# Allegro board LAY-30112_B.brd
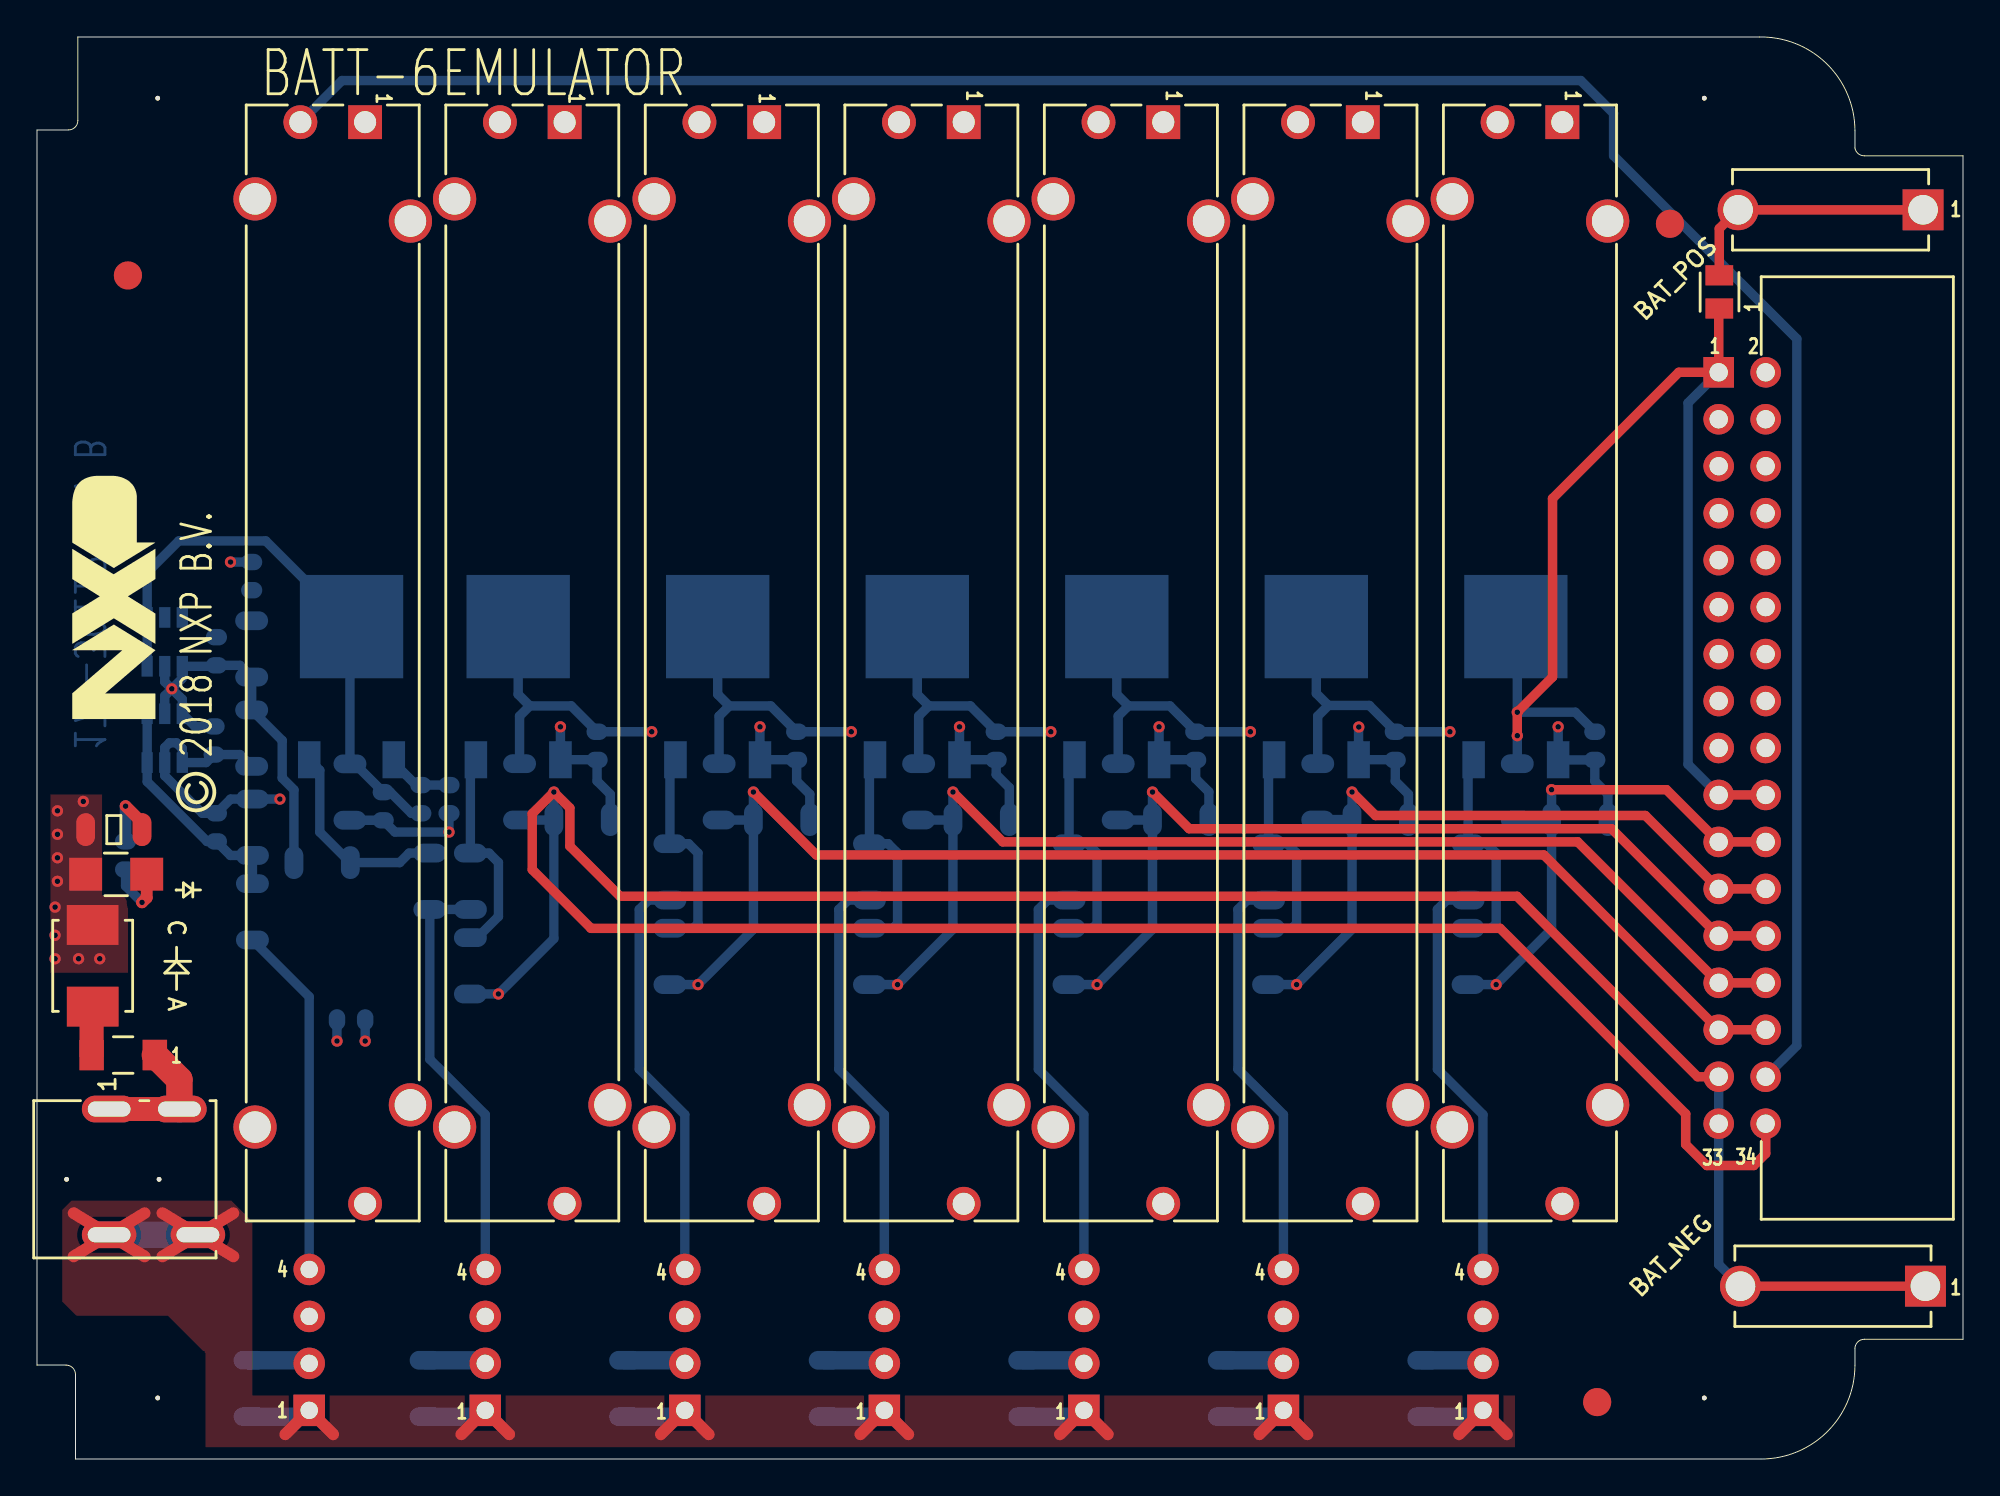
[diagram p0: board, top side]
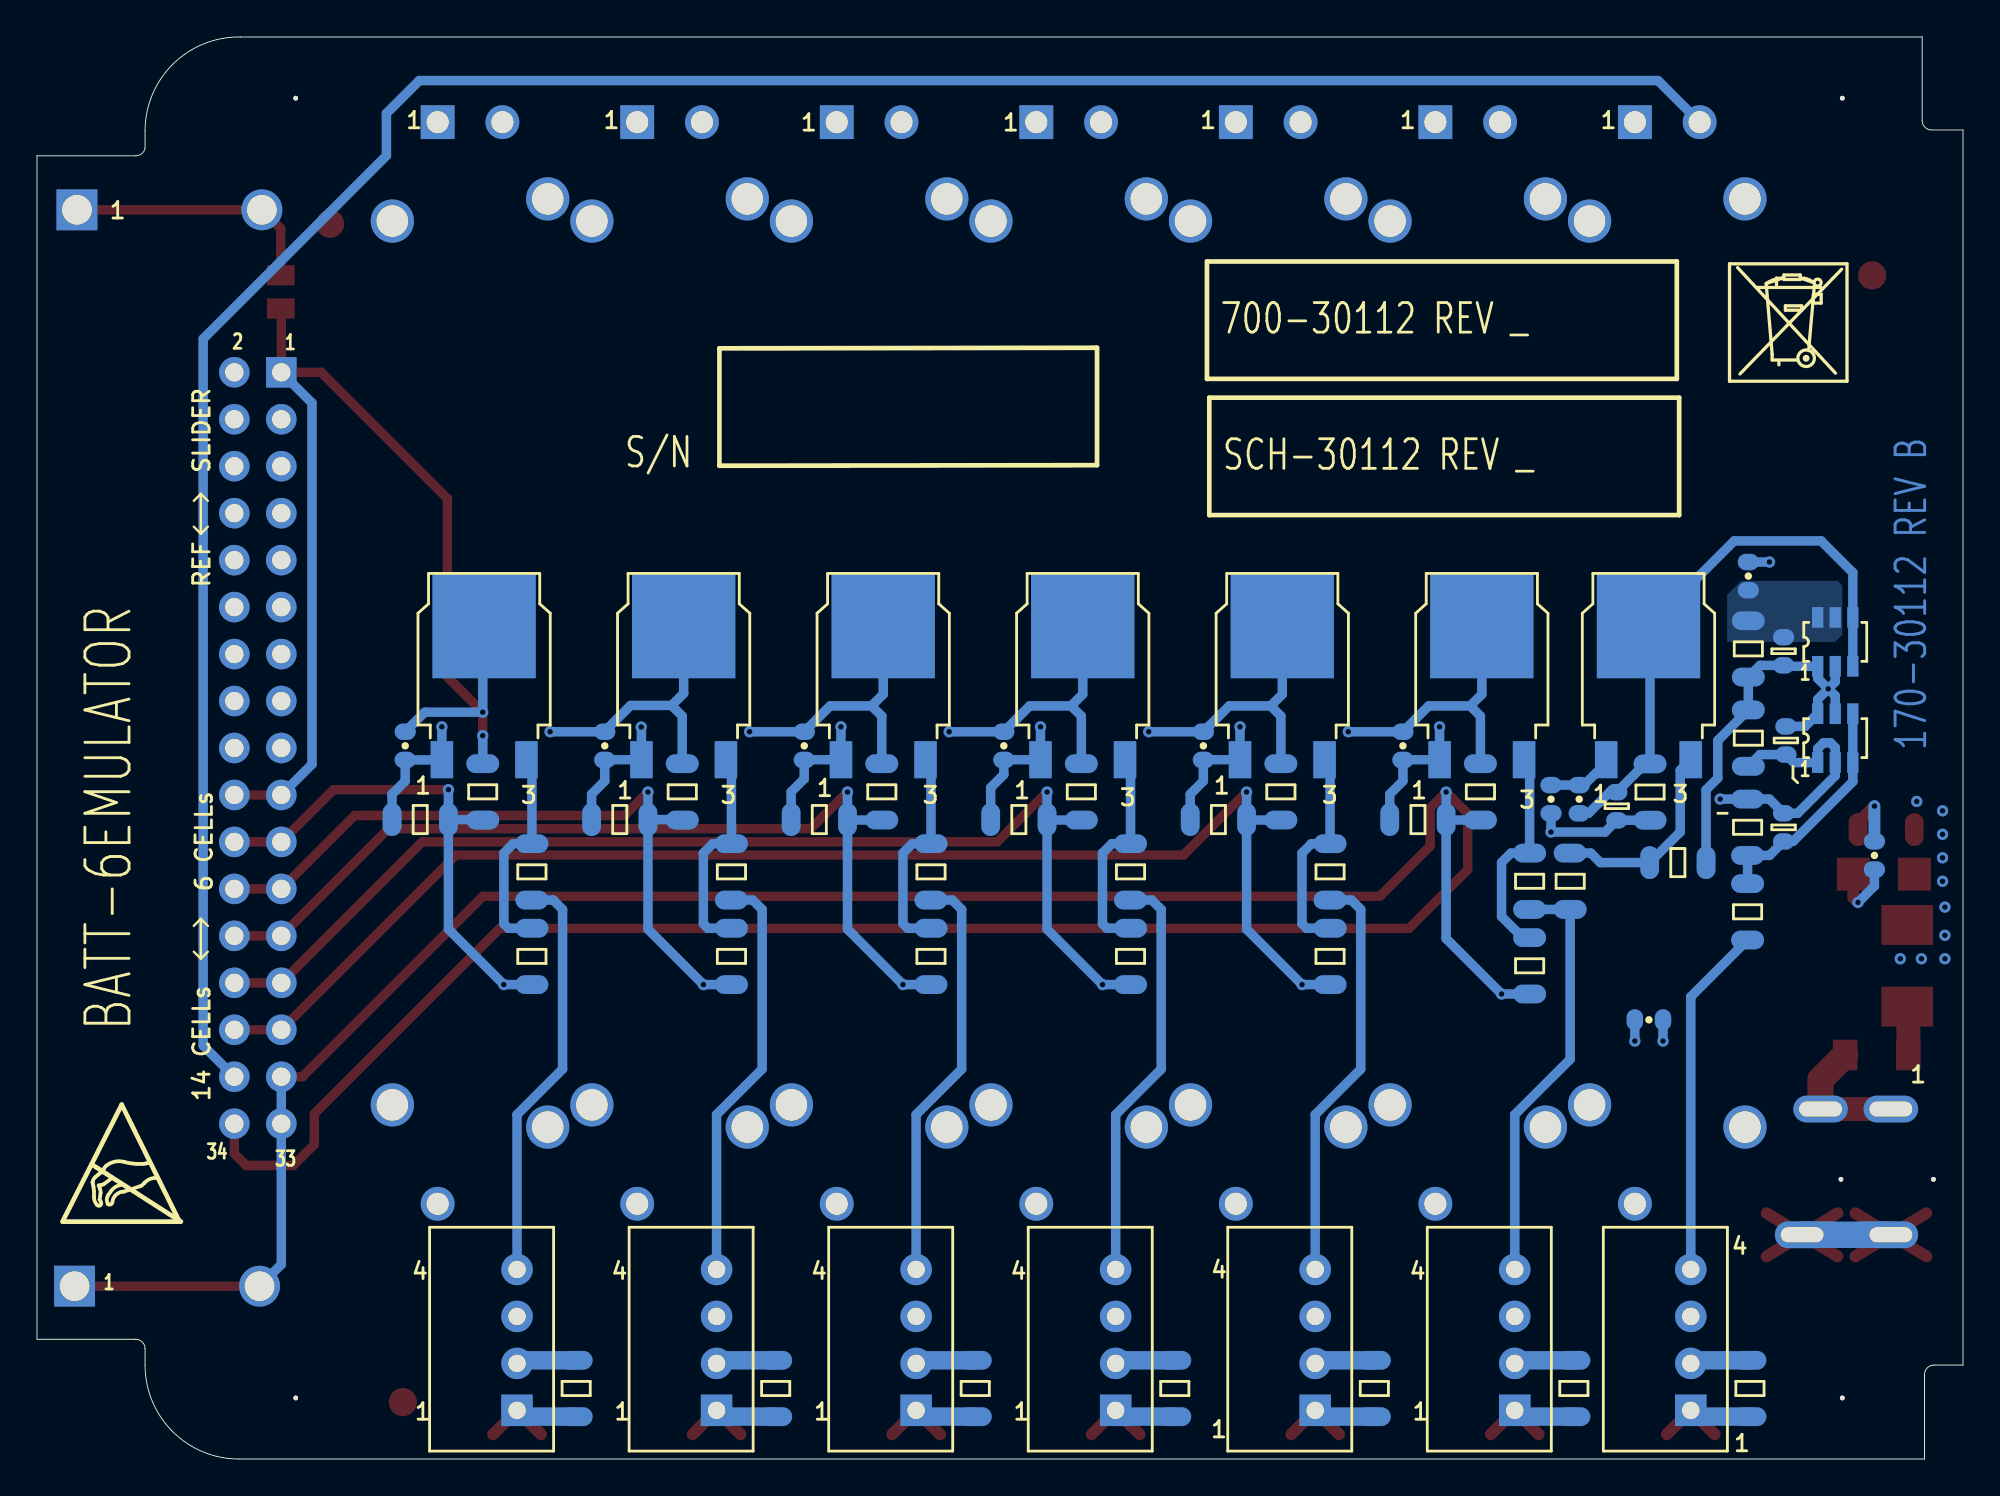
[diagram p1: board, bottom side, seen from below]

Outline 104.13 x 76.91 mm; copper layers: TOP, L2_SIG1, L3_SIG2, BOTTOM. Coordinates in mm from the lower left corner of the outline.
Outline path: 0,71.88 0,5.08 1.57,5.08 arc(1.93,4.93) 2.08,4.57 2.08,0 93.2,0 arc(96.8,1.49) 98.28,5.08 98.28,5.97 arc(98.43,6.33) 98.79,6.48 104.13,6.48 104.13,70.49 98.78,70.49 arc(98.46,70.6) 98.28,70.9 98.28,71.83 arc(96.77,75.46) 93.12,76.91 2.21,76.91 2.21,72.39 arc(2.06,72.03) 1.7,71.88 0,71.88

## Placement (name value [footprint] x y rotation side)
C29  1UF  [CC1206_OV]  29.47 34.59 180 bottom
C30  10uF  [CC1206_OV]  23.43 26.68 270 bottom
C31  100uF  [CC1206_OV]  26.09 36.08 270 bottom
C32  10uF  [CC1206_OV]  21.04 3.82 270 bottom
C37  10uF  [CC1206_OV]  34.22 27.18 270 bottom
C38  1UF  [CC1206_OV]  40.26 34.59 180 bottom
C39  100uF  [CC1206_OV]  36.88 36.08 270 bottom
C40  10uF  [CC1206_OV]  31.83 3.82 270 bottom
C41  10uF  [CC1206_OV]  45.01 27.18 270 bottom
C42  1UF  [CC1206_OV]  51.04 34.59 180 bottom
C43  100uF  [CC1206_OV]  47.67 36.08 270 bottom
C44  10uF  [CC1206_OV]  42.61 3.82 270 bottom
C45  1UF  [CC1206_OV]  61.83 34.59 180 bottom
C46  10uF  [CC1206_OV]  55.79 27.18 270 bottom
C47  100uF  [CC1206_OV]  58.45 36.08 270 bottom
C48  10uF  [CC1206_OV]  53.4 3.82 270 bottom
C49  1UF  [CC1206_OV]  72.62 34.59 180 bottom
C50  10uF  [CC1206_OV]  66.58 27.18 270 bottom
C51  100uF  [CC1206_OV]  69.24 36.08 270 bottom
C52  10uF  [CC1206_OV]  64.19 3.82 270 bottom
C53  10uF  [CC1206_OV]  77.37 27.18 270 bottom
C54  1UF  [CC1206_OV]  83.41 34.59 180 bottom
C55  100uF  [CC1206_OV]  80.03 36.08 270 bottom
C56  10uF  [CC1206_OV]  74.98 3.82 270 bottom
C63  10uF  [CC1206_OV]  15.42 32.26 180 bottom
C64  10uF  [CC1206_OV]  16.92 36.07 270 bottom
C65  10uF  [CC1206_OV]  11.52 3.82 270 bottom
C66  10uF  [CC1206_OV]  11.65 34.17 90 bottom
C67  10uF  [CC1206_OV]  11.61 38.99 270 bottom
C68  47uF  [CC1206_OV]  4.15 34.04 0 top
C69  10uF  [CC1206_OV]  11.61 43.81 270 bottom
C70  0.1uF  [CC0603_OV]  18.72 35.31 270 bottom
C71  0.1uF  [CC0603_OV]  9.7 43.69 270 bottom
C72  0.1uF  [CC0603_OV]  9.7 34.16 90 bottom
C73  0.1uF  [CC0603_OV]  9.57 38.86 270 bottom
D2  LED RED  [1206LD]  4.28 31.63 180 top
D3  SS24T3G  [CASE403A_03]  3.01 26.68 270 top
F1  SF-1206SP400-2  [FUSE_3P2X1P65]  4.66 21.85 180 top
F2  F0805B0R25FSTR  [FUSE_1P8_2P2X1P5]  90.95 63.12 90 top
J1  CON 2x17  [HDR217_RA_TH]  90.92 58.78 0 top
J2  BANANA RED  [BANANA_930224]  101.97 67.56 180 top
J6  PJ-053DH  [CON_3_DC_PWR_JACK_TH]  3.9 18.93 270 top
J23  BANANA BLACK  [BANANA_930224]  102.09 9.35 180 top
NOREF  -  []  33.36 17.95 90 top
NOREF#2  -  []  67.39 10.25 0 top
NOREF#3  -  []  28.78 -11.14 90 top
NOREF#4  -  [unnamed#2]  90.14 73.6 0 top
NOREF#5  -  []  33.22 -11.14 0 top
NOREF#6  -  []  93.4 63.77 0 top
NOREF#7  -  [unnamed#2]  84.35 3.08 0 top
NOREF#8  -  []  52.55 66.95 90 top
NOREF#9  -  []  45.81 10.25 0 top
NOREF#10  -  []  22.58 17.95 90 top
NOREF#11  -  []  14.72 2.63 90 top
NOREF#12  -  []  8.7 12.13 90 top
NOREF#13  -  []  90.92 18.14 0 top
NOREF#14  -  []  54.64 13.05 90 top
NOREF#15  -  []  6.26 19.47 0 top
NOREF#16  -  []  41.76 19.15 90 top
NOREF#17  -  []  1.35 19.2 90 top
NOREF#18  -  []  35.81 72.3 0 top
NOREF#19  -  []  0 5.9 0 top
NOREF#20  -  []  78.17 10.25 0 top
NOREF#21  -  []  46.6 72.3 0 top
NOREF#22  -  []  24.23 2.63 90 top
NOREF#23  -  []  35.81 72.3 0 top
NOREF#24  -  [unnamed#2]  90.14 3.3 0 top
NOREF#25  -  []  84.92 19.15 90 top
NOREF#26  -  []  6.57 12.36 0 top
NOREF#27  -  []  1.6 15.13 0 top
NOREF#28  -  []  2.95 21.85 0 top
NOREF#29  -  []  82.72 -11.14 90 top
NOREF#30  -  []  76.37 -11.14 0 top
NOREF#31  -  []  1.35 28.7 0 top
NOREF#32  -  []  6.57 0.61 90 top
NOREF#33  -  []  12.92 12.36 0 top
NOREF#34  -  []  50.36 -11.14 90 top
NOREF#35  -  []  44.01 0.61 0 top
NOREF#36  -  []  14.24 72.3 0 top
NOREF#37  -  []  57.39 72.3 0 top
NOREF#38  -  []  65.73 17.95 90 top
NOREF#39  -  []  65.43 13.05 90 top
NOREF#40  -  []  30.98 19.15 90 top
NOREF#41  -  []  44.01 -11.14 0 top
NOREF#42  -  []  22.43 0.61 0 top
NOREF#43  -  []  54.94 17.95 90 top
NOREF#44  -  []  30.98 66.95 90 top
NOREF#45  -  []  -16.87 -28.01 0 top
NOREF#46  -  []  6.57 0.61 0 top
NOREF#47  -  []  104.13 7.77 0 top
NOREF#48  -  []  84.92 66.95 90 top
NOREF#49  -  []  76.22 13.05 90 top
NOREF#50  -  []  90.92 18.14 90 top
NOREF#51  -  []  -464.54 -272.99 0 top
NOREF#52  -  []  46.6 72.3 0 top
NOREF#53  -  []  67.39 2.63 90 top
NOREF#54  -  []  61.15 -11.14 90 top
NOREF#55  -  [unnamed#2]  6.53 73.6 0 top
NOREF#56  -  []  1.6 15.13 0 top
NOREF#57  -  []  57.39 72.3 0 top
NOREF#58  -  []  76.37 0.61 0 top
NOREF#59  -  []  76.52 17.95 90 top
NOREF#60  -  []  24.23 10.25 0 top
NOREF#61  -  []  11.49 13.05 90 top
NOREF#62  -  []  2.96 76.91 0 top
NOREF#63  -  []  65.59 -11.14 0 top
NOREF#64  -  []  22.43 -11.14 0 top
NOREF#65  -  []  76.22 73.05 0 top
NOREF#66  -  []  6.53 73.6 0 top
NOREF#67  -  []  20.19 66.95 90 top
NOREF#68  -  []  33.06 13.05 90 top
NOREF#69  -  []  20.19 19.15 90 top
NOREF#70  -  []  71.94 -11.14 90 top
NOREF#71  -  [unnamed#2]  6.53 3.3 0 top
NOREF#72  -  []  25.03 72.3 0 top
NOREF#73  -  []  25.03 72.3 0 top
NOREF#74  -  []  54.64 73.05 0 top
NOREF#75  -  []  -438.51 252.15 0 top
NOREF#76  -  []  6.53 3.3 0 top
NOREF#77  -  []  54.8 0.61 0 top
NOREF#78  -  []  78.97 72.3 0 top
NOREF#79  -  []  45.81 2.63 90 top
NOREF#80  -  []  6.53 3.3 0 top
NOREF#81  -  []  43.85 73.05 0 top
NOREF#82  -  []  14.24 72.3 0 top
NOREF#83  -  []  78.17 2.63 90 top
NOREF#84  -  []  2.08 1.28 0 top
NOREF#85  -  []  52.55 19.15 90 top
NOREF#86  -  []  65.59 0.61 0 top
NOREF#87  -  []  35.02 10.25 0 top
NOREF#88  -  []  22.28 73.05 0 top
NOREF#89  -  []  63.34 66.95 90 top
NOREF#90  -  []  93.46 23.22 0 top
NOREF#91  -  []  6.53 3.3 0 top
NOREF#92  -  []  6.4 40.03 90 top
NOREF#93  -  []  43.85 13.05 90 top
NOREF#94  -  []  90.14 3.3 0 top
NOREF#95  -  []  11.79 17.95 90 top
NOREF#96  -  []  44.15 17.95 90 top
NOREF#97  -  []  56.6 10.25 0 top
NOREF#98  -  []  74.13 66.95 90 top
NOREF#99  -  []  8.62 36.07 90 top
NOREF#100  -  []  33.06 73.05 0 top
NOREF#101  -  [unnamed#2]  88.28 66.81 0 top
NOREF#102  -  []  69.58 61.21 0 top
NOREF#103  -  []  1.6 15.13 90 top
NOREF#104  -  []  144.02 63.77 90 top
NOREF#105  -  []  74.13 19.15 90 top
NOREF#106  -  []  41.76 66.95 90 top
NOREF#107  -  []  98.49 70.58 0 top
NOREF#108  -  []  22.28 13.05 90 top
NOREF#109  -  []  68.18 72.3 0 top
NOREF#110  -  []  -30.59 -92.83 0 top
NOREF#111  -  []  2.44 0 0 top
NOREF#112  -  []  0.59 5.08 0 top
NOREF#113  -  []  56.6 2.63 90 top
NOREF#114  -  []  96.35 75.82 0 top
NOREF#115  -  []  98.28 5.2 0 top
NOREF#116  -  []  39.57 -11.14 90 top
NOREF#117  -  []  3.9 18.93 90 top
NOREF#118  -  []  33.22 0.61 0 top
NOREF#119  -  []  35.02 2.63 90 top
NOREF#120  -  []  7.7 18.93 90 top
NOREF#121  -  [unnamed#2]  4.92 64.01 0 top
NOREF#122  -  []  65.43 73.05 0 top
NOREF#123  -  []  63.34 19.15 90 top
NOREF#124  -  []  78.97 72.3 0 top
NOREF#125  -  []  1.6 15.13 0 top
NOREF#126  -  []  54.8 -11.14 0 top
NOREF#127  -  []  68.18 72.3 0 top
NOREF#128  -  []  11.49 73.05 0 top
NOREF#129  -  []  0.88 71.88 0 top
NOREF#130  -  []  6.26 19.47 90 top
NOREF#131  -  []  12.62 58.29 180 bottom
NOREF#132  -  []  67.23 53.72 180 bottom
NOREF#133  -  []  40.87 58.42 180 bottom
NOREF#134  -  []  86.97 56.13 180 bottom
NOREF#135  -  []  40.75 51.05 180 bottom
NOREF#136  -  []  102.72 12.84 180 bottom
R36  340.0  [RC0603_OV]  30.28 38.57 270 bottom
R40  340.0  [RC0603_OV]  41.07 38.57 270 bottom
R42  340.0  [RC0603_OV]  51.86 38.57 270 bottom
R44  340.0  [RC0603_OV]  62.64 38.57 270 bottom
R46  340.0  [RC0603_OV]  73.43 38.57 270 bottom
R48  340.0  [RC0603_OV]  84.22 38.57 270 bottom
R75  22  [RC1206_OV]  77.37 31.76 270 bottom
R76  22  [RC1206_OV]  66.58 31.76 270 bottom
R77  22  [RC1206_OV]  55.79 31.76 270 bottom
R78  22  [RC1206_OV]  45.01 31.76 270 bottom
R79  22  [RC1206_OV]  34.22 31.76 270 bottom
R80  22  [RC1206_OV]  23.43 31.25 270 bottom
R84  1k  [POT_PTA45_TH]  82.47 72.3 270 top
R85  1k  [POT_PTA45_TH]  71.68 72.3 270 top
R86  1k  [POT_PTA45_TH]  60.89 72.3 270 top
R87  1k  [POT_PTA45_TH]  50.1 72.3 270 top
R88  1k  [POT_PTA45_TH]  39.31 72.3 270 top
R89  1k  [POT_PTA45_TH]  28.53 72.3 270 top
R99  22  [RC1206_OV]  21.24 31.25 90 bottom
R100  1k  [POT_PTA45_TH]  17.74 72.3 270 top
R101  3.3K  [RC0603_OV]  11.61 47.75 90 bottom
R102  22  [RC1206_OV]  11.65 29.6 270 bottom
R104  3.3K  [RC0603_OV]  16.98 23.75 180 bottom
R105  560  [RC0603_OV]  4.79 32.64 90 bottom
R107  340.0  [RC0603_OV]  20.75 35.69 90 bottom
R108  1.02K  [RC0603_OV]  22.27 35.69 270 bottom
U16  ZLDO1117KTC  [TO252_B]  26.01 41.93 180 bottom
U17  TME1209S  [SIP4_2P54_11P5X6P1]  24.23 2.63 0 bottom
U20  ZLDO1117KTC  [TO252_B]  36.8 41.93 180 bottom
U21  TME1209S  [SIP4_2P54_11P5X6P1]  35.02 2.63 0 bottom
U22  ZLDO1117KTC  [TO252_B]  47.59 41.93 180 bottom
U23  TME1209S  [SIP4_2P54_11P5X6P1]  45.81 2.63 0 bottom
U24  ZLDO1117KTC  [TO252_B]  58.38 41.93 180 bottom
U25  TME1209S  [SIP4_2P54_11P5X6P1]  56.6 2.63 0 bottom
U26  ZLDO1117KTC  [TO252_B]  69.17 41.93 180 bottom
U27  TME1209S  [SIP4_2P54_11P5X6P1]  67.39 2.63 0 bottom
U28  ZLDO1117KTC  [TO252_B]  79.95 41.93 180 bottom
U29  TME1209S  [SIP4_2P54_11P5X6P1]  78.17 2.63 0 bottom
U30  ZLDO1117KTC  [TO252_B]  17 41.93 180 bottom
U31  TME1205S  [SIP4_2P54_11P5X6P1]  14.72 2.63 0 bottom
U32  ADR3412ARJZ-R2  [SOT23-6]  6.91 38.99 180 bottom
U33  ADR3412ARJZ-R2  [SOT23-6]  6.91 44.2 180 bottom

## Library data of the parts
C29-C32 C37-C56 C63-C73 = CAP_NP
D2 = LED
D3 = DIODE_SCHTKY
F1 F2 = FUSE
J1 = CONN_HDR_17X2
J2 J23 = BANANA_SOCKET
J6 = DC_PWR_JACK_4P
R36 R40 R42 R44 R46 R48 R75-R80 R99 R101 R102 R104 R105 R107 R108 = RES
R84-R89 R100 = POT
U16 U20 U22 U24 U26 U28 U30 = ZLDO1117_TO252_3P
U17 U21 U23 U25 U27 U29 U31 = NKE0505SC_SIP_4P
U32 U33 = ADR34XX_SOT23_6P

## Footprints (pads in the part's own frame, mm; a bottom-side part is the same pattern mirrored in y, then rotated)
1206LD
  rect 1.778x1.778 smd: A(1.651,0) C(-1.651,0)
BANANA_930224
  rect 2.21x2.21 hole 1.6: 1(0,0)
  round 2.21 hole 1.6: 2(10,0)
CASE403A_03
  rect 2.159x2.794 smd: A(2.21,0) C(-2.21,0)
CC0603_OV
  oval 0.889x1.143 smd: 1(-0.762,0) 2(0.762,0)
CC1206_OV
  oval 1.016x1.778 smd: 1(-1.524,0) 2(1.524,0)
CON_3_DC_PWR_JACK_TH
  round 0.254 hole 1.016 unplated: (3.8,2.7) (3.8,-2.3)
  oval 1.448x2.946 hole 0.813x2.311: 1(0,0) 2(6.8,0) 3(6.8,4.8) 4(0,3.8)
FUSE_1P8_2P2X1P5
  rect 1.092x1.499 smd: 1(-0.896,0) 2(0.896,0)
FUSE_3P2X1P65
  rect 1.321x1.651 smd: 1(-1.71,0) 2(1.71,0)
HDR217_RA_TH
  rect 1.651x1.651 hole 0.991: 1(0,0)
  round 1.651 hole 0.991: 2(2.54,0) 3(0,-2.54) 4(2.54,-2.54) 5(0,-5.08) 6(2.54,-5.08) 7(0,-7.62) 8(2.54,-7.62) 9(0,-10.16) 10(2.54,-10.16) 11(0,-12.7) 12(2.54,-12.7) 13(0,-15.24) 14(2.54,-15.24) 15(0,-17.78) 16(2.54,-17.78) 17(0,-20.32) 18(2.54,-20.32) 19(0,-22.86) 20(2.54,-22.86) 21(0,-25.4) 22(2.54,-25.4) 23(0,-27.94) 24(2.54,-27.94) 25(0,-30.48) 26(2.54,-30.48) 27(0,-33.02) 28(2.54,-33.02) 29(0,-35.56) 30(2.54,-35.56) 31(0,-38.1) 32(2.54,-38.1) 33(0,-40.64) 34(2.54,-40.64)
POT_PTA45_TH
  round 2.337 hole 1.702: (4.15,-5.95) (5.35,2.45) (53.15,2.45) (54.35,-5.95)
  rect 1.829x1.829 hole 1.194: 1(0,0)
  round 1.829 hole 1.194: 2(0,-3.5) 3(58.5,0)
RC0603_OV
  oval 0.889x1.143 smd: 1(-0.762,0) 2(0.762,0)
RC1206_OV
  oval 1.016x1.778 smd: 1(-1.524,0) 2(1.524,0)
SIP4_2P54_11P5X6P1
  rect 1.702x1.702 hole 0.94: 1(0,0)
  round 1.702 hole 0.94: 2(0,-2.54) 3(0,-5.08) 4(0,-7.62)
SOT23-6
  rect 0.61x1.118 smd: 1(-0.95,-1.321) 2(0,-1.321) 3(0.95,-1.321) 4(0.95,1.321) 5(0,1.321) 6(-0.95,1.321)
TO252_B
  rect 1.219x2.007 smd: 1(-2.285,-4.105) 3(2.285,-4.105)
  rect 5.588x5.588 smd: 2(0,3.095)
unnamed#2
  round 0.254 hole 3.556 unplated: (0,0)

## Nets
12V: C32.1 C40.1 C44.1 C48.1 C52.1 C56.1 C65.1 C68.1 D2.A(ANODE) D3.C U17.2(+VIN) U21.2(+VIN) U23.2(+VIN) U25.2(+VIN) U27.2(+VIN) U29.2(+VIN) U31.2(+VIN)
GND: C32.2 C40.2 C44.2 C48.2 C52.2 C56.2 C65.2 C68.2 J6.2 J6.3 R105.2 U17.1(-VIN) U21.1(-VIN) U23.1(-VIN) U25.1(-VIN) U27.1(-VIN) U29.1(-VIN) U31.1(-VIN)
CT01: C31.1 C37.2 C38.2 C39.2 J1.29(A15) J1.30(B15) R36.1 R88.2(WIPER) R88.3(B) U16.2(VOUT) U21.3(-VOUT)
CT02: C39.1 C41.2 C42.2 C43.2 J1.27(A14) J1.28(B14) R40.1 R87.2(WIPER) R87.3(B) U20.2(VOUT) U23.3(-VOUT)
CT03: C43.1 C45.2 C46.2 C47.2 J1.25(A13) J1.26(B13) R42.1 R86.2(WIPER) R86.3(B) U22.2(VOUT) U25.3(-VOUT)
CT04: C47.1 C49.2 C50.2 C51.2 J1.23(A12) J1.24(B12) R44.1 R85.2(WIPER) R85.3(B) U24.2(VOUT) U27.3(-VOUT)
CT05: C51.1 C53.2 C54.2 C55.2 J1.21(A11) J1.22(B11) R46.1 R84.2(WIPER) R84.3(B) U26.2(VOUT) U29.3(-VOUT)
CT06: C55.1 F2.1 J1.1(A1) J1.2(B1) J1.19(A10) J1.20(B10) R48.1 U28.2(VOUT)
CTREF: C29.2 C30.2 C31.2 C63.2 C64.2 C67.1 C69.2 C70.2 C71.2 C73.1 J1.31(A16) J1.33(A17) J1.34(B17) J23.1 J23.2 R89.2(WIPER) R89.3(B) R108.2 U17.3(-VOUT) U32.5(VOUT_SENSE) U32.6(VOUT_FORCE) U33.1(GND_FORCE) U33.2(GND_SENSE)
SENSE_N: J1.32(B16) R100.2(WIPER)
TERM_P: F2.2 J2.1 J2.2
N20569083: R80.2 R99.1 U17.4(+VOUT)
N20569101: R79.2 U21.4(+VOUT)
N20569111: R78.2 U23.4(+VOUT)
N20569121: R77.2 U25.4(+VOUT)
N20569131: R76.2 U27.4(+VOUT)
N20569138: R75.2 U29.4(+VOUT)
N20569265: C38.1 R40.2 R88.1(A) U20.1(ADJ(GND))
N20569267: C37.1 R79.1 U20.3(VIN)
N20569746: F1.1 J6.1(PIN) J6.4
N20569785: C29.1 R36.2 R89.1(A) U16.1(ADJ(GND))
N20569787: C30.1 R80.1 U16.3(VIN)
N20570018: C42.1 R42.2 R87.1(A) U22.1(ADJ(GND))
N20570029: C41.1 R78.1 U22.3(VIN)
N20570212: C45.1 R44.2 R86.1(A) U24.1(ADJ(GND))
N20570214: C46.1 R77.1 U24.3(VIN)
N20570385: C49.1 R46.2 R85.1(A) U26.1(ADJ(GND))
N20570387: C50.1 R76.1 U26.3(VIN)
N20570805: C54.1 R48.2 R84.1(A) U28.1(ADJ(GND))
N20570807: C53.1 R75.1 U28.3(VIN)
N20571679: C63.1 R99.2 U30.3(VIN)
N20596346: D2.C(CATHODE) R105.1
N20609936: D3.A F1.2
N20623751: C69.1 C71.1 R101.1 U33.5(VOUT_SENSE) U33.6(VOUT_FORCE)
N20623763: C66.2 C67.2 C72.2 C73.2 R104.2 U31.3(-VOUT) U32.1(GND_FORCE) U32.2(GND_SENSE)
N20623769: C66.1 C72.1 R102.1 U32.3(ENABLE) U32.4(VIN)
N20623781: C64.1 C70.1 R107.1 U30.2(VOUT) U33.3(ENABLE) U33.4(VIN)
N20623783: R107.2 R108.1 U30.1(ADJ(GND))
N20623803: R100.1(A) R101.2
N20623964: R102.2 U31.4(+VOUT)
N20624012: R100.3(B) R104.1

Pads without a net: J1 3 4 5 6 7 8 9 10 11 12 13 14 15 16 17 18

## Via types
v1: diameter 0.61, hole 0.305, TOP to BOTTOM, 43 vias

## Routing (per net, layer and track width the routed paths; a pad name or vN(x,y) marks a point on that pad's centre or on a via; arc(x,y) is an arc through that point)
12V: length 44.8
  L2_SIG1 w0.635: 66.28,4.07 U27.2 68.49,4.07 ; 23.13,4.07 U17.2 25.34,4.07 ; 57.71,4.07 U25.2 55.49,4.07 ; 13.61,4.07 U31.2 15.82,4.07 ; 36.13,4.07 U21.2 33.92,4.07 ; 44.7,4.07 U23.2 46.92,4.07 ; 77.07,4.07 U29.2 79.28,4.07
  BOTTOM w0.991: U17.2 24.07,5.34 C32.1 ; C48.1 56.43,5.34 U25.2 ; C40.1 34.86,5.34 U21.2 ; C52.1 67.22,5.34 U27.2 ; C44.1 45.64,5.34 U23.2 ; U29.2 78.01,5.34 C56.1 ; U31.2 14.55,5.34 C65.1
  vias: v1(0.98,29.85) v1(0.98,28.33) v1(0.98,27.06) v1(1.11,35.06) v1(1.11,33.79) v1(1.11,32.52) v1(1.11,31.25) v1(2.25,27.06) v1(2.5,35.57) v1(3.39,27.06)
GND: length 137.1
  TOP w0.635: 6.78,13.3 J6.3 ; J6.3 10.62,13.3 ; J6.3 10.62,10.96 ; J6.3 6.78,10.96 ; 1.98,10.96 J6.2 ; J6.2 1.98,13.3 ; J6.2 5.82,10.96 ; J6.2 5.82,13.3 ; C68.2 5.68,34.42 v1(4.79,35.31) ; 68.68,1.34 U27.1 66.09,1.34 ; 47.11,1.34 U23.1 44.51,1.34 ; 57.89,1.34 U25.1 55.3,1.34 ; 36.32,1.34 U21.1 33.73,1.34 ; 25.53,1.34 U17.1 22.94,1.34 ; 79.47,1.34 U29.1 76.88,1.34 ; 16.01,1.34 U31.1 13.42,1.34
  L3_SIG2 w0.635: 33.92,1.53 U21.1 ; U21.1 36.13,3.74 ; U21.1 33.92,3.74 ; U21.1 36.13,1.53 ; 77.07,1.53 U29.1 ; U29.1 79.28,3.74 ; U29.1 79.28,1.53 ; U29.1 77.07,3.74 ; U31.1 15.82,1.53 ; U31.1 13.61,1.53 ; U31.1 13.61,3.74 ; U31.1 15.82,3.74 ; U23.1 46.92,3.74 ; U23.1 46.92,1.53 ; U23.1 44.7,3.74 ; U23.1 44.7,1.53 ; 6.78,13.3 J6.3 ; J6.3 6.78,10.96 ; J6.3 10.62,10.96 ; J6.3 10.62,13.3 ; U27.1 68.49,3.74 ; U27.1 68.49,1.53 ; U27.1 66.28,3.74 ; U27.1 66.28,1.53 ; 23.13,3.74 U17.1 ; U17.1 25.34,1.53 ; U17.1 25.34,3.74 ; U17.1 23.13,1.53 ; U25.1 57.71,1.53 ; U25.1 55.49,3.74 ; U25.1 55.49,1.53 ; U25.1 57.71,3.74 ; J6.2 5.82,13.3 ; J6.2 5.82,10.96 ; J6.2 1.98,13.3 ; J6.2 1.98,10.96
  BOTTOM w0.635: v1(4.79,35.31) R105.2
  BOTTOM w0.991: C44.2 45.47,2.29 U23.1 ; C56.2 77.83,2.29 U29.1 ; U25.1 56.26,2.29 C48.2 ; C65.2 14.38,2.29 U31.1 ; U17.1 23.89,2.29 C32.2 ; C52.2 67.05,2.29 U27.1 ; C40.2 34.68,2.29 U21.1
  BOTTOM w1.422: J6.2 J6.3
CT01: length 106.3
  TOP w0.508: v1(38.73,36.07) 42.14,32.67 81.46,32.67 J1.29 J1.30
  L2_SIG1 w0.635: 33.92,8.82 U21.3 36.13,8.82 ; 34.66,73.46 R88.2 ; R88.2 36.97,71.15 ; R88.2 36.97,73.46 ; R88.2 34.66,71.15 ; 38.16,12.65 R88.3 ; R88.3 40.47,14.96 ; R88.3 38.16,14.96 ; R88.3 40.47,12.65
  BOTTOM w0.508: C31.1 26.09,40.18 26.64,40.73 ; C38.2 38.71,34.56 C39.2 ; C38.2 v1(38.73,36.07) ; C38.2 38.73,28.66 v1(35.74,25.66) C37.2 ; 26.64,40.73 28.88,40.73 R36.1 v1(33.24,39.33) ; 26.64,40.73 26.01,41.36 U16.2
CT02: length 94.5
  TOP w0.508: J1.28 J1.27 83.29,33.38 52.21,33.38 v1(49.52,36.07)
  L2_SIG1 w0.635: 48.95,12.65 R87.3 ; R87.3 51.25,12.65 ; R87.3 48.95,14.96 ; R87.3 51.25,14.96 ; 45.45,73.46 R87.2 ; R87.2 47.75,73.46 ; R87.2 47.75,71.15 ; R87.2 45.45,71.15 ; 46.92,8.82 U23.3 44.7,8.82
  BOTTOM w0.508: C39.1 36.88,40.18 37.43,40.73 ; C42.2 49.49,34.56 C43.2 ; C42.2 v1(49.52,36.07) ; C42.2 49.52,28.66 v1(46.52,25.66) C41.2 ; v1(44.02,39.33) R40.1 39.67,40.73 37.43,40.73 ; U20.2 36.8,41.36 37.43,40.73
CT03: length 82.6
  TOP w0.508: v1(60.31,36.07) 62.29,34.09 85.12,34.09 J1.25 J1.26
  L2_SIG1 w0.635: 59.74,12.65 R86.3 ; R86.3 62.04,14.96 ; R86.3 62.04,12.65 ; R86.3 59.74,14.96 ; 55.49,8.82 U25.3 57.71,8.82 ; 56.24,71.15 R86.2 ; R86.2 56.24,73.46 ; R86.2 58.54,73.46 ; R86.2 58.54,71.15
  BOTTOM w0.508: C45.2 60.28,34.56 C47.2 ; C45.2 v1(60.31,36.07) ; C45.2 60.31,28.66 v1(57.31,25.66) C46.2 ; C43.1 47.67,40.18 48.22,40.73 ; U22.2 47.59,41.36 48.22,40.73 ; 48.22,40.73 50.46,40.73 R42.1 v1(54.81,39.33)
CT04: length 70.8
  TOP w0.508: J1.24 J1.23 86.95,34.8 72.37,34.8 v1(71.1,36.07)
  L2_SIG1 w0.635: R85.2 69.33,71.15 ; R85.2 67.03,71.15 ; R85.2 69.33,73.46 ; R85.2 67.03,73.46 ; 70.53,14.96 R85.3 ; R85.3 72.83,12.65 ; R85.3 70.53,12.65 ; R85.3 72.83,14.96 ; 68.49,8.82 U27.3 66.28,8.82
  BOTTOM w0.508: 59,40.73 58.45,40.18 C47.1 ; 59,40.73 58.38,41.36 U24.2 ; 59,40.73 61.25,40.73 R44.1 v1(65.6,39.33) ; C50.2 v1(68.1,25.66) 71.1,28.66 C49.2 ; C49.2 69.27,34.59 C51.2 ; C49.2 v1(71.1,36.07)
CT05: length 59.2
  TOP w0.508: J1.22 J1.21 88.09,36.2 v1(81.88,36.2)
  L2_SIG1 w0.635: 77.07,8.82 U29.3 79.28,8.82 ; 77.81,73.46 R84.2 ; R84.2 77.81,71.15 ; R84.2 80.12,73.46 ; R84.2 80.12,71.15 ; 81.31,14.96 R84.3 ; R84.3 83.62,14.96 ; R84.3 83.62,12.65 ; R84.3 81.31,12.65
  BOTTOM w0.508: 69.82,40.76 69.24,40.18 C51.1 ; 69.82,40.76 69.17,41.41 U26.2 ; 69.82,40.76 72.03,40.76 73.43,39.36 R46.1 v1(76.39,39.33) ; C53.2 v1(78.89,25.66) 81.88,28.66 C54.2 ; C54.2 80.05,34.59 C55.2 ; C54.2 v1(81.88,36.2)
CT06: length 97.1
  TOP w0.508: F2.1 90.92,62.2 J1.1 88.76,58.78 81.93,51.95 81.93,42.3 v1(80.03,40.39) v1(80.03,39.12) ; J1.19 J1.20
  L3_SIG2 w0.508: v1(80.03,39.12) v1(80.03,40.39) 80.03,52.2 88.28,60.46 91.78,60.46 J1.2
  BOTTOM w0.508: v1(80.03,39.12) C55.1 ; J1.1 89.26,57.12 89.26,37.57 J1.19 ; U28.2 80.03,44.94 v1(80.03,40.39) 83.16,40.39 R48.1
CTREF: length 234.5
  TOP w0.508: J1.31 89.78,20.68 80.02,30.43 31.52,30.43 28.81,33.15 28.81,35.21 v1(27.94,36.07) 26.78,34.91 26.78,31.88 29.95,28.7 79.1,28.7 89.13,18.67 89.13,17.02 90.28,15.88 92.82,15.88 93.46,16.52 J1.34 ; J23.1 J23.2
  L2_SIG1 w0.635: R89.2 26.18,73.46 ; R89.2 23.87,71.15 ; R89.2 23.87,73.46 ; R89.2 26.18,71.15 ; 23.13,8.82 U17.3 25.34,8.82 ; 27.37,12.65 R89.3 ; R89.3 27.37,14.96 ; R89.3 29.68,12.65 ; R89.3 29.68,14.96
  BOTTOM w0.508: 22.27,34.93 v1(22.27,33.91) 19.35,33.91 C70.2 18.71,34.55 C64.2 ; 6.91,40.31 6.91,41.27 v1(7.29,41.66) ; v1(7.29,41.66) 7.86,41.09 U32.6 8.54,39.62 C73.1 ; v1(7.29,41.66) 7.86,42.22 U33.1 9.65,42.88 C71.2 10.97,42.93 C69.2 C67.1 13.26,38.86 13.26,36.83 13.89,36.2 C63.2 ; v1(7.29,41.66) 6.91,42.04 U33.2 ; C29.2 27.92,34.56 C31.2 ; C29.2 27.94,28.15 v1(24.95,25.15) C30.2 ; C29.2 v1(27.94,36.07) ; J23.2 90.92,10.52 J1.33 J1.31
SENSE_N: length 129.6
  BOTTOM w0.508: R100.2 16.49,74.55 83.46,74.55 85.24,72.78 85.24,70.49 95.14,60.58 95.14,22.36 J1.32
TERM_P: length 14
  TOP w0.508: J2.1 J2.2 90.95,66.55 F2.2
N20569083: length 22.9
  BOTTOM w0.508: U17.4 24.23,18.63 21.24,21.62 R99.1 R80.2
N20569101: length 22.4
  BOTTOM w0.508: U21.4 35.02,18.63 32.56,21.09 32.56,29.72 33.07,30.23 R79.2
N20569111: length 22.4
  BOTTOM w0.508: R78.2 43.86,30.23 43.35,29.72 43.35,21.09 45.81,18.63 U23.4
N20569121: length 22.4
  BOTTOM w0.508: R77.2 54.64,30.23 54.14,29.72 54.14,21.09 56.6,18.63 U25.4
N20569131: length 22.4
  BOTTOM w0.508: U27.4 67.39,18.63 64.92,21.09 64.92,29.72 65.43,30.23 R76.2
N20569138: length 22.4
  BOTTOM w0.508: R75.2 76.22,30.23 75.71,29.72 75.71,21.09 78.17,18.63 U29.4
N20569265: length 44.6
  L3_SIG2 w0.508: R88.1 39.31,65.59 33.67,59.95 33.67,45.01 v1(39.09,39.6)
  BOTTOM w0.508: C38.1 41.78,35.96 41.07,36.67 R40.2 41.06,37.82 U20.1 v1(39.09,39.6)
N20569267: length 11.8
  BOTTOM w0.508: U20.3 34.22,37.52 R79.1 35.23,33.28 35.74,32.77 35.74,28.95 35.49,28.71 C37.1
N20569746: length 7.3
  TOP w1.295: J6.4 J6.1
  TOP w1.422: J6.4 7.7,20.52 F1.1
N20569785: length 43.6
  L3_SIG2 w0.508: R89.1 28.53,64.07 24.02,59.57 24.02,43.88 v1(28.3,39.6)
  BOTTOM w0.508: C29.1 30.99,35.96 30.28,36.67 R36.2 30.27,37.82 U16.1 v1(28.3,39.6)
N20569787: length 11.8
  BOTTOM w0.508: U16.3 23.43,37.52 R80.1 24.44,32.77 24.95,32.26 24.95,29.34 23.8,28.2 C30.1
N20570018: length 44.6
  L3_SIG2 w0.508: v1(49.87,39.6) 44.47,45 44.47,58.04 50.1,63.68 R87.1
  BOTTOM w0.508: C42.1 52.57,36.31 51.86,37.02 R42.2 51.85,37.82 U22.1 v1(49.87,39.6)
N20570029: length 11.8
  BOTTOM w0.508: U22.3 45.01,37.52 R78.1 46.02,33.28 46.52,32.77 46.52,28.95 46.28,28.71 C41.1
N20570212: length 44.2
  L3_SIG2 w0.508: R86.1 60.89,63.29 55.65,58.04 55.65,44.62 v1(60.66,39.6)
  BOTTOM w0.508: v1(60.66,39.6) U24.1 62.63,37.82 R44.2 62.64,36.79 63.36,36.08 C45.1
N20570214: length 11.8
  BOTTOM w0.508: U24.3 55.79,37.52 R77.1 56.8,33.28 57.31,32.77 57.31,28.95 57.06,28.71 C46.1
N20570385: length 43.8
  L3_SIG2 w0.508: R85.1 71.68,63.79 66.95,59.06 66.95,44.1 v1(71.46,39.59)
  BOTTOM w0.508: C49.1 74.14,35.96 73.43,36.67 R46.2 73.42,37.82 U26.1 71.45,39.58 v1(71.46,39.59)
N20570387: length 11.8
  BOTTOM w0.508: U26.3 66.58,37.52 R76.1 67.59,33.28 68.1,32.77 68.1,28.95 67.85,28.71 C50.1
N20570805: length 47.6
  L3_SIG2 w0.508: v1(82.24,39.6) 80.62,37.98 79.27,37.98 78,39.25 78,56.52 82.24,60.76 82.24,72.08 R84.1
  BOTTOM w0.508: C54.1 84.93,35.96 84.22,36.67 R48.2 82.25,37.81 U28.1 v1(82.24,39.6)
N20570807: length 11.8
  BOTTOM w0.508: C53.1 78.64,28.71 78.89,28.95 78.89,32.77 78.38,33.28 R75.1 77.37,37.52 U28.3
N20571679: length 11
  BOTTOM w0.508: U30.3 15.29,37.25 15.29,33.91 C63.1 19.61,32.26 20.12,32.77 R99.2
N20596346: length 3.8
  TOP w0.635: D2.C 5.93,30.36 v1(5.68,30.1)
  BOTTOM w0.508: R105.1 4.79,30.99 v1(5.68,30.1)
N20609936: length 2.6
  TOP w1.295: D3.A 2.95,24.41 F1.2
N20623763: length 19.3
  L3_SIG2 w0.635: 13.61,8.82 U31.3 15.82,8.82
  BOTTOM w0.508: v1(13.13,35.69) C66.2 10.47,35.69 C72.2 8.94,34.93 6.91,36.96 U32.2 6.91,38.48 7.16,38.73 7.54,38.73 7.86,38.42 U32.1 9.14,37.67 C73.2 10.97,38.1 C67.2 ; R104.2 v1(16.22,22.61)
N20623769: length 12.5
  BOTTOM w0.508: R102.1 C66.1 10.46,32.64 C72.1 9.19,33.4 5.96,36.64 U32.3 U32.4
N20623781: length 31.1
  BOTTOM w0.508: U33.3 U33.4 5.96,47.95 7.67,49.66 12.37,49.66 U30.2 16.92,44.94 C64.1 17.19,37.6 C70.1 19.1,36.07 20.24,34.93 20.75,34.93
N20623783: length 3.7
  BOTTOM w0.508: U30.1 19.29,37.66 20.5,36.45 R107.2 R108.1
N20623803: length 27.9
  L3_SIG2 w0.508: R100.1 17.74,64.17 10.46,56.9 v1(10.46,48.51)
  BOTTOM w0.508: R101.2 v1(10.46,48.51)
N20623964: length 19.1
  BOTTOM w0.508: R102.2 14.72,25 U31.4
N20624012: length 4.4
  L3_SIG2 w0.635: 18.89,14.96 R100.3 18.89,12.65
  BOTTOM w0.508: R104.1 v1(17.74,22.61)

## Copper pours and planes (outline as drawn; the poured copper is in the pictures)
12V on TOP: 3.52,35.95 0.72,35.95 0.72,26.29 4.92,26.29 4.92,30.49 3.52,30.49
12V on L2_SIG1: 0.72,8.9 8.95,0.67 80.66,0.67 80.66,5.47 13.18,5.47 10.38,8.27 10.38,25.91 8.09,25.91 8.09,30.36 4.92,30.36 4.92,34.3 3.01,34.3 3.01,36.33 0.72,36.33
GND on TOP: 10.5,13.98 1.87,13.98 1.36,13.47 1.36,8.51 2.12,7.75 7.07,7.75 9.11,5.72 9.11,0.64 79.9,0.64 79.9,3.43 11.65,3.43 11.65,12.83
GND on L3_SIG2: 0.72,8.9 8.98,0.64 80.66,0.64 80.66,4.2 14.44,4.2 11.01,7.63 11.01,25.91 8.09,25.91 8.09,30.36 5.04,30.36 5.04,35.69 3.01,35.69 3.01,27.69 3.9,27.69 3.9,26.17 0.72,26.17
CT01 on L2_SIG1: 33.07,76.08 33.07,7.24 42.21,7.24 42.21,76.08
CT02 on L2_SIG1: 43.86,76.08 43.86,7.24 53,7.24 53,76.08
CT03 on L2_SIG1: 54.64,76.08 54.64,7.24 63.79,7.24 63.79,76.08
CT04 on L2_SIG1: 65.43,76.08 65.43,7.24 74.58,7.24 74.58,76.08
CT05 on L2_SIG1: 76.22,76.08 76.22,7.24 85.36,7.24 85.36,76.08
CTREF on L2_SIG1: 16.98,11.31 16.98,7.24 31.42,7.24 31.42,76.08 7.58,76.08 7.58,71.12 6.65,71.12 6.65,39.88 7.58,39.88 7.58,32.39 10.12,32.39 10.12,28.2 13.93,28.2 13.93,11.31
N20623751 on BOTTOM: 11.99,47.5 6.78,47.5 6.53,47.24 6.53,44.58 6.91,44.2 12.75,44.2 12.75,46.74
N20623763 on L3_SIG2: 12.66,36.2 16.47,36.2 16.47,7.88 16.09,7.5 14.06,7.5 12.66,8.9
N20624012 on L3_SIG2: 16.98,41.28 16.98,11.94 20.54,11.94 20.54,41.28

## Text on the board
BOTTOM: 7 OF 10 | SECONDARY SIDE | 170-30112 REV B
Board Geometry/Soldermask Bottom: 8 OF 10 | SECONDARY SOLDERMASK
Ref Des/Silkscreen Bottom: 6 CELLs | SLIDER | REF | 14 CELLs | 9 OF 10 | SECONDARY SILKSCREEN | BATT-6EMULATOR
User.Comments: CR_MODULE1X2_7 | 1 | 33 | 2 | 34 | PCB EDGE | 1 OF 1 | TEST PROBE | J1 | 1/1 | - | +
TOP: 4 OF 10 | PRIMARY SIDE
Board Geometry/Soldermask Top: 3 OF 10 | PRIMARY SOLDERMASK
Ref Des/Silkscreen Top: BAT_NEG | BAT_POS | 2 OF 10 | PRIMARY SILKSCREEN | BATT-6EMULATOR
L2_SIG1: 5 OF 10 | INTERNAL LAYER 1
L3_SIG2: 6 OF 10 | INTERNAL LAYER 2
DIMENSION: .062" THK +/- 10% | 2X | 4X | PRIMARY DATUM | GRID ORIGIN
BODY_CENTER: 16 | 17 | 8
PASTEMASK_TOP: 1 OF 10 | PASTEMASK TOP
User.5: 10 OF 10 | SECONDARY PASTEMASK
User.16: 12-14-17 | 02-19-18 | C.N. | A1 | B | SILK FIX | RESPIN PER ECO81323
User.21: FIGURE | SIZE | 12.0 | 37.0 | 39.0 | 47.0 | 63.0 | 67.0 | 40.0 | 140.0 | 91.0x32.0 | DRILL CHART: TOP to BOTTOM | ALL UNITS ARE IN MILS | TOLERANCE | +0.0/-12.0 | +3.0/-3.0 | +2.0/-2.0 | PLATED | NON-PLATED | QTY | 43 | 28 | 34 | 21 | 4 | 2
